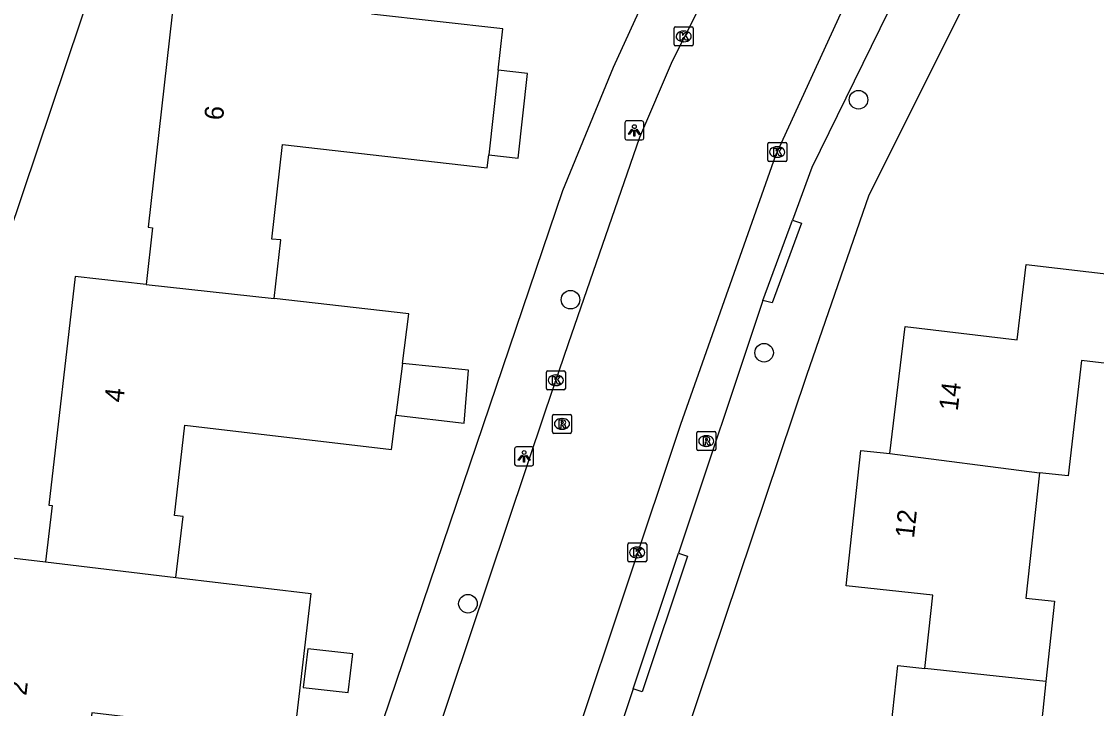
# Model space of a CAD drawing. Extents: x 162398 to 163643, y 386453 to 387397.
# Drawn here: x 162713.1 to 162769.7, y 386684.2 to 386720.4 of the extents above; entities that cross this region are included whole.
import ezdxf

# ---------------------------------------------------------------- set-up
doc = ezdxf.new("R2010")
doc.units = 0
for name, color, linetype in [('IMGEO_Boom', 7, 'Continuous'), ('IMGEO_Kolk', 7, 'Continuous'), ('IMGEO_Lichtpunt', 7, 'Continuous'), ('IMGEO_Pand', 7, 'Continuous'), ('IMGEO_Pand_nummerreeks', 7, 'Continuous'), ('IMGEO_Rijbaan_lokaal_open', 7, 'Continuous'), ('IMGEO_Rioolput', 7, 'Continuous'), ('IMGEO_Voetpad_open', 7, 'Continuous')]:
    doc.layers.add(name, color=color, linetype=linetype)

msp = doc.modelspace()

# ---------------------------------------------------------------- linework, layer by layer
at = {"layer": 'IMGEO_Boom'}
for centre in [(162757.172, 386716.289), (162742.004, 386705.757), (162752.201, 386702.964), (162736.602, 386689.743)]:
    msp.add_circle(centre, 0.489, dxfattribs=at)
at = {"layer": 'IMGEO_Kolk'}
for p, q in [((162747.466, 386719.201), (162747.466, 386720.053)), ((162747.541, 386720.127), (162748.393, 386720.127)), ((162747.954, 386719.907), (162747.979, 386719.907)), ((162748.467, 386720.053), (162748.467, 386719.201)), ((162747.977, 386719.347), (162747.952, 386719.347)), ((162748.393, 386719.127), (162747.541, 386719.127)), ((162752.394, 386713.11), (162752.394, 386713.962)), ((162752.469, 386714.036), (162753.321, 386714.036)), ((162752.882, 386713.816), (162752.907, 386713.816)), ((162753.395, 386713.962), (162753.395, 386713.11)), ((162753.321, 386713.036), (162752.469, 386713.036)), ((162752.905, 386713.256), (162752.88, 386713.256)), ((162740.735, 386701.086), (162740.735, 386701.938)), ((162740.81, 386702.012), (162741.662, 386702.012)), ((162741.223, 386701.792), (162741.248, 386701.792)), ((162741.736, 386701.938), (162741.736, 386701.086)), ((162741.246, 386701.232), (162741.221, 386701.232)), ((162741.662, 386701.012), (162740.81, 386701.012)), ((162745.017, 386692.018), (162745.017, 386692.87)), ((162745.092, 386692.944), (162745.944, 386692.944)), ((162745.505, 386692.724), (162745.53, 386692.724)), ((162746.018, 386692.87), (162746.018, 386692.018)), ((162745.528, 386692.164), (162745.503, 386692.164)), ((162745.944, 386691.944), (162745.092, 386691.944))]:
    msp.add_line(p, q, dxfattribs=at)
for points in [[(162747.466, 386719.201), (162747.466, 386720.053)], [(162747.541, 386720.127), (162748.393, 386720.127)], [(162747.787, 386719.827), (162747.91, 386719.827), (162747.91, 386719.676), (162748.04, 386719.827), (162748.204, 386719.827), (162748.058, 386719.676), (162748.211, 386719.427), (162748.059, 386719.427), (162747.974, 386719.591), (162747.91, 386719.524), (162747.91, 386719.427), (162747.787, 386719.427), (162747.787, 386719.827)], [(162748.467, 386720.053), (162748.467, 386719.201)], [(162748.393, 386719.127), (162747.541, 386719.127)], [(162752.394, 386713.11), (162752.394, 386713.962)], [(162752.469, 386714.036), (162753.321, 386714.036)], [(162752.715, 386713.736), (162752.838, 386713.736), (162752.838, 386713.585), (162752.968, 386713.736), (162753.132, 386713.736), (162752.986, 386713.585), (162753.139, 386713.336), (162752.987, 386713.336), (162752.902, 386713.5), (162752.838, 386713.433), (162752.838, 386713.336), (162752.715, 386713.336), (162752.715, 386713.736)], [(162753.395, 386713.962), (162753.395, 386713.11)], [(162753.321, 386713.036), (162752.469, 386713.036)], [(162740.735, 386701.086), (162740.735, 386701.938)], [(162740.81, 386702.012), (162741.662, 386702.012)], [(162741.056, 386701.712), (162741.179, 386701.712), (162741.179, 386701.561), (162741.309, 386701.712), (162741.473, 386701.712), (162741.327, 386701.561), (162741.48, 386701.312), (162741.328, 386701.312), (162741.243, 386701.476), (162741.179, 386701.409), (162741.179, 386701.312), (162741.056, 386701.312), (162741.056, 386701.712)], [(162741.736, 386701.938), (162741.736, 386701.086)], [(162741.662, 386701.012), (162740.81, 386701.012)], [(162745.017, 386692.018), (162745.017, 386692.87)], [(162745.092, 386692.944), (162745.944, 386692.944)], [(162745.338, 386692.644), (162745.461, 386692.644), (162745.461, 386692.493), (162745.591, 386692.644), (162745.755, 386692.644), (162745.609, 386692.493), (162745.762, 386692.244), (162745.61, 386692.244), (162745.525, 386692.408), (162745.461, 386692.341), (162745.461, 386692.244), (162745.338, 386692.244), (162745.338, 386692.644)], [(162746.018, 386692.87), (162746.018, 386692.018)], [(162745.944, 386691.944), (162745.092, 386691.944)]]:
    msp.add_lwpolyline(points, dxfattribs=at)
for centre, start, end in [((162747.543, 386720.051), 91.552, 178.448), ((162747.543, 386720.051), 91.552, 178.448), ((162748.391, 386720.051), 1.552, 88.448), ((162748.391, 386720.051), 1.552, 88.448), ((162747.543, 386719.203), 181.552, 268.448), ((162747.543, 386719.203), 181.552, 268.448), ((162748.391, 386719.203), 271.552, 358.448), ((162748.391, 386719.203), 271.552, 358.448), ((162752.471, 386713.96), 91.552, 178.448), ((162752.471, 386713.96), 91.552, 178.448), ((162753.319, 386713.96), 1.552, 88.448), ((162753.319, 386713.96), 1.552, 88.448), ((162752.471, 386713.112), 181.552, 268.448), ((162752.471, 386713.112), 181.552, 268.448), ((162753.319, 386713.112), 271.552, 358.448), ((162753.319, 386713.112), 271.552, 358.448), ((162740.812, 386701.936), 91.552, 178.448), ((162740.812, 386701.936), 91.552, 178.448), ((162741.66, 386701.936), 1.552, 88.448), ((162741.66, 386701.936), 1.552, 88.448), ((162740.812, 386701.088), 181.552, 268.448), ((162740.812, 386701.088), 181.552, 268.448), ((162741.66, 386701.088), 271.552, 358.448), ((162741.66, 386701.088), 271.552, 358.448), ((162745.094, 386692.868), 91.552, 178.448), ((162745.094, 386692.868), 91.552, 178.448), ((162745.942, 386692.868), 1.552, 88.448), ((162745.942, 386692.868), 1.552, 88.448), ((162745.094, 386692.02), 181.552, 268.448), ((162745.094, 386692.02), 181.552, 268.448), ((162745.942, 386692.02), 271.552, 358.448), ((162745.942, 386692.02), 271.552, 358.448)]:
    msp.add_arc(centre, 0.0765, start, end, dxfattribs=at)
for centre, major_axis, ratio, start_param, end_param in [((162747.953, 386719.627), (-0.387, 0.002), 0.722429, 4.712389, 7.853982), ((162747.978, 386719.627), (-0.39, 0.002), 0.717154, 1.570796, 4.712389), ((162752.881, 386713.536), (-0.387, 0.002), 0.722429, 4.712389, 7.853982), ((162752.906, 386713.536), (-0.39, 0.002), 0.717154, 1.570796, 4.712389), ((162741.222, 386701.512), (-0.387, 0.002), 0.722429, 4.712389, 7.853982), ((162741.247, 386701.512), (-0.39, 0.002), 0.717154, 1.570796, 4.712389), ((162745.504, 386692.444), (-0.387, 0.002), 0.722429, 4.712389, 7.853982), ((162745.529, 386692.444), (-0.39, 0.002), 0.717154, 1.570796, 4.712389)]:
    msp.add_ellipse(centre, major_axis=major_axis, ratio=ratio, start_param=start_param, end_param=end_param, dxfattribs=at)
at = {"layer": 'IMGEO_Lichtpunt'}
for p, q in [((162744.868, 386715.077), (162744.868, 386714.27)), ((162744.868, 386715.077), (162744.868, 386714.27)), ((162745.77, 386715.172), (162744.962, 386715.172)), ((162745.77, 386715.172), (162744.962, 386715.172)), ((162745.864, 386714.27), (162745.864, 386715.077)), ((162745.864, 386714.27), (162745.864, 386715.077)), ((162744.962, 386714.176), (162745.77, 386714.176)), ((162744.962, 386714.176), (162745.77, 386714.176)), ((162739.062, 386697.909), (162739.062, 386697.102)), ((162739.062, 386697.909), (162739.062, 386697.102)), ((162739.964, 386698.004), (162739.156, 386698.004)), ((162739.964, 386698.004), (162739.156, 386698.004)), ((162740.058, 386697.102), (162740.058, 386697.909)), ((162740.058, 386697.102), (162740.058, 386697.909)), ((162739.156, 386697.008), (162739.964, 386697.008)), ((162739.156, 386697.008), (162739.964, 386697.008))]:
    msp.add_line(p, q, dxfattribs=at)
for points in [[(162745.242, 386714.741), (162745.281, 386714.713), (162745.093, 386714.451), (162745.055, 386714.478), (162745.242, 386714.741)], [(162745.344, 386714.693), (162745.391, 386714.693), (162745.391, 386714.371), (162745.344, 386714.371), (162745.344, 386714.693)], [(162745.454, 386714.713), (162745.492, 386714.74), (162745.679, 386714.478), (162745.64, 386714.45), (162745.454, 386714.713)], [(162739.436, 386697.573), (162739.475, 386697.545), (162739.287, 386697.283), (162739.249, 386697.31), (162739.436, 386697.573)], [(162739.538, 386697.525), (162739.585, 386697.525), (162739.585, 386697.203), (162739.538, 386697.203), (162739.538, 386697.525)], [(162739.648, 386697.545), (162739.686, 386697.572), (162739.873, 386697.31), (162739.834, 386697.282), (162739.648, 386697.545)]]:
    msp.add_lwpolyline(points, dxfattribs=at)
for centre in [(162745.367, 386714.875), (162739.561, 386697.707)]:
    msp.add_circle(centre, 0.0994, dxfattribs=at)
for centre, start, end in [((162744.962, 386715.077), 90, 180), ((162744.962, 386715.077), 90, 180), ((162745.77, 386715.077), 0, 90), ((162745.77, 386715.077), 0, 90), ((162744.962, 386714.27), 180, 270), ((162744.962, 386714.27), 180, 270), ((162745.77, 386714.27), 270, 0), ((162745.77, 386714.27), 270, 360), ((162739.156, 386697.909), 90, 180), ((162739.156, 386697.909), 90, 180), ((162739.964, 386697.909), 0, 90), ((162739.964, 386697.909), 0, 90), ((162739.156, 386697.102), 180, 270), ((162739.156, 386697.102), 180, 270), ((162739.964, 386697.102), 270, 0), ((162739.964, 386697.102), 270, 360)]:
    msp.add_arc(centre, 0.0946, start, end, dxfattribs=at)
at = {"layer": 'IMGEO_Pand'}
for points in [[(162724.697, 386721.66), (162721.171, 386722.057), (162719.763, 386709.572), (162719.989, 386709.546), (162719.653, 386706.562)], [(162738.2, 386717.839), (162738.446, 386720.025), (162731.518, 386720.806)], [(162738.2, 386717.839), (162737.699, 386713.39)], [(162737.699, 386713.39), (162739.247, 386713.216), (162739.748, 386717.665), (162738.2, 386717.839)], [(162726.396, 386705.815), (162726.745, 386708.902), (162726.282, 386708.954), (162726.842, 386713.927), (162737.622, 386712.711), (162737.699, 386713.39)], [(162758.82, 386697.649), (162759.637, 386704.341), (162765.532, 386703.651), (162765.995, 386707.61), (162770.962, 386707.029), (162772.97, 386706.794), (162775.28, 386706.524), (162774.735, 386701.869), (162768.924, 386702.549), (162768.21, 386696.484), (162766.702, 386696.645)], [(162719.653, 386706.562), (162715.909, 386706.984), (162714.527, 386694.94), (162714.704, 386694.919), (162714.356, 386691.953)], [(162719.653, 386706.562), (162726.396, 386705.815)], [(162733.152, 386702.403), (162733.482, 386705.016), (162726.396, 386705.815)], [(162733.152, 386702.403), (162732.808, 386699.677)], [(162732.808, 386699.677), (162736.399, 386699.246), (162736.63, 386702.051), (162733.152, 386702.403)], [(162721.221, 386691.125), (162721.598, 386694.342), (162721.142, 386694.395), (162721.699, 386699.151), (162732.58, 386697.874), (162732.808, 386699.677)], [(162760.672, 386686.327), (162761.087, 386690.195), (162756.529, 386690.684), (162757.294, 386697.812), (162758.82, 386697.649)], [(162758.82, 386697.649), (162766.702, 386696.645)], [(162766.702, 386696.645), (162765.993, 386690.033), (162767.493, 386689.873), (162767.039, 386685.642)], [(162721.221, 386691.125), (162728.337, 386690.29), (162727.451, 386682.742), (162716.795, 386683.992), (162716.238, 386679.246), (162716.64, 386679.199), (162716.14, 386674.932), (162709.333, 386675.731), (162709.678, 386678.67), (162709.318, 386678.712), (162710.919, 386692.356), (162714.356, 386691.953)], [(162714.356, 386691.953), (162721.221, 386691.125)], [(162727.928, 386685.337), (162730.3, 386685.058), (162730.54, 386687.097), (162728.167, 386687.375), (162727.928, 386685.337)], [(162767.039, 386685.642), (162766.876, 386684.117), (162766.343, 386679.145), (162762.799, 386679.525), (162762.236, 386674.275), (162752.728, 386675.295), (162753.556, 386683.015), (162758.807, 386682.452), (162759.239, 386686.481), (162760.672, 386686.327)], [(162767.039, 386685.642), (162760.672, 386686.327)]]:
    msp.add_lwpolyline(points, dxfattribs=at)
at = {"layer": 'IMGEO_Rijbaan_lokaal_open'}
for points in [[(162710.091, 386702.248), (162726.132, 386750), (162726.172, 386750.119), (162726.376, 386750.623), (162726.624, 386751.108), (162726.914, 386751.568), (162727.244, 386752.001), (162727.611, 386752.402), (162728.013, 386752.769), (162728.446, 386753.099), (162728.907, 386753.389), (162729.392, 386753.636), (162729.896, 386753.839), (162730.417, 386753.996), (162730.95, 386754.106), (162731.491, 386754.168), (162732.035, 386754.181), (162732.578, 386754.146), (162758.569, 386751.236), (162760.491, 386750), (162762.044, 386749.001)], [(162730.673, 386670.035), (162730.769, 386670.321), (162740.68, 386699.903), (162741.907, 386703.446), (162745.663, 386714.324), (162747.378, 386718.341), (162751.779, 386727.044), (162755.937, 386733.921), (162764.605, 386747.471)], [(162739.403, 386674.014), (162747.82, 386699.195), (162752.818, 386713.374), (162756.44, 386721.247), (162760.497, 386728.254), (162767.447, 386739.091), (162769.561, 386742.426)]]:
    msp.add_lwpolyline(points, dxfattribs=at)
at = {"layer": 'IMGEO_Rioolput'}
for p, q in [((162741.055, 386698.789), (162741.055, 386699.641)), ((162741.13, 386699.715), (162741.982, 386699.715)), ((162741.543, 386699.495), (162741.568, 386699.495)), ((162742.056, 386699.641), (162742.056, 386698.789)), ((162741.566, 386698.935), (162741.541, 386698.935)), ((162741.982, 386698.715), (162741.13, 386698.715)), ((162748.655, 386697.886), (162748.655, 386698.738)), ((162748.73, 386698.812), (162749.582, 386698.812)), ((162749.143, 386698.592), (162749.168, 386698.592)), ((162749.656, 386698.738), (162749.656, 386697.886)), ((162749.582, 386697.812), (162748.73, 386697.812)), ((162749.166, 386698.032), (162749.141, 386698.032))]:
    msp.add_line(p, q, dxfattribs=at)
for points in [[(162741.055, 386698.789), (162741.055, 386699.641)], [(162741.13, 386699.715), (162741.982, 386699.715)], [(162741.644, 386699.413), (162741.392, 386699.415), (162741.392, 386699.015)], [(162742.056, 386699.641), (162742.056, 386698.789)], [(162741.392, 386699.015), (162741.516, 386699.015), (162741.516, 386699.177), (162741.527, 386699.177)], [(162741.57, 386699.334), (162741.516, 386699.334), (162741.516, 386699.253)], [(162741.516, 386699.253), (162741.568, 386699.253)], [(162741.574, 386699.148), (162741.645, 386699.015), (162741.785, 386699.015), (162741.72, 386699.141)], [(162741.982, 386698.715), (162741.13, 386698.715)], [(162748.655, 386697.886), (162748.655, 386698.738)], [(162748.73, 386698.812), (162749.582, 386698.812)], [(162749.244, 386698.51), (162748.992, 386698.512), (162748.992, 386698.112)], [(162748.992, 386698.112), (162749.116, 386698.112), (162749.116, 386698.274), (162749.127, 386698.274)], [(162749.17, 386698.431), (162749.116, 386698.431), (162749.116, 386698.35)], [(162749.116, 386698.35), (162749.168, 386698.35)], [(162749.656, 386698.738), (162749.656, 386697.886)], [(162749.582, 386697.812), (162748.73, 386697.812)], [(162749.174, 386698.245), (162749.245, 386698.112), (162749.385, 386698.112), (162749.32, 386698.238)]]:
    msp.add_lwpolyline(points, dxfattribs=at)
for centre, radius, start, end in [((162741.132, 386699.639), 0.0765, 91.552, 178.448), ((162741.132, 386699.639), 0.0765, 91.552, 178.448), ((162741.643, 386699.303), 0.109, 350.3612, 89.416), ((162741.98, 386699.639), 0.0765, 1.552, 88.448), ((162741.98, 386699.639), 0.0765, 1.552, 88.448), ((162741.526, 386699.124), 0.0533, 26.0293, 88.6989), ((162741.552, 386699.442), 0.19, 274.7715, 282.9687), ((162741.576, 386699.238), 0.0964, 77.0061, 93.1865), ((162741.59, 386699.295), 0.0378, 276.6634, 79.6772), ((162741.641, 386699.303), 0.112, 277.5842, 350.9817), ((162741.625, 386699.088), 0.108, 29.5134, 73.7905), ((162741.132, 386698.791), 0.0765, 181.552, 268.448), ((162741.132, 386698.791), 0.0765, 181.552, 268.448), ((162741.98, 386698.791), 0.0765, 271.552, 358.448), ((162741.98, 386698.791), 0.0765, 271.552, 358.448), ((162748.732, 386698.736), 0.0765, 91.552, 178.448), ((162748.732, 386698.736), 0.0765, 91.552, 178.448), ((162749.126, 386698.221), 0.0533, 26.0293, 88.6989), ((162749.152, 386698.539), 0.19, 274.7715, 282.9687), ((162749.176, 386698.335), 0.0964, 77.0061, 93.1865), ((162749.19, 386698.392), 0.0378, 276.6634, 79.6772), ((162749.243, 386698.4), 0.109, 350.3612, 89.416), ((162749.241, 386698.4), 0.112, 277.5842, 350.9817), ((162749.225, 386698.185), 0.108, 29.5134, 73.7905), ((162749.58, 386698.736), 0.0765, 1.552, 88.448), ((162749.58, 386698.736), 0.0765, 1.552, 88.448), ((162748.732, 386697.888), 0.0765, 181.552, 268.448), ((162748.732, 386697.888), 0.0765, 181.552, 268.448), ((162749.58, 386697.888), 0.0765, 271.552, 358.448), ((162749.58, 386697.888), 0.0765, 271.552, 358.448)]:
    msp.add_arc(centre, radius, start, end, dxfattribs=at)
for centre, major_axis, ratio, start_param, end_param in [((162741.542, 386699.215), (-0.387, 0.002), 0.722429, 4.712389, 7.853982), ((162741.567, 386699.215), (-0.39, 0.002), 0.717154, 1.570796, 4.712389), ((162749.142, 386698.312), (-0.387, 0.002), 0.722429, 4.712389, 7.853982), ((162749.167, 386698.312), (-0.39, 0.002), 0.717154, 1.570796, 4.712389)]:
    msp.add_ellipse(centre, major_axis=major_axis, ratio=ratio, start_param=start_param, end_param=end_param, dxfattribs=at)
at = {"layer": 'IMGEO_Voetpad_open'}
for points in [[(162762.044, 386749.001), (162752.537, 386734.127), (162746.835, 386723.64), (162744.257, 386717.994), (162741.576, 386711.487), (162727.566, 386670.164)], [(162744.409, 386671.894), (162754.454, 386701.785), (162757.742, 386711.279), (162762.934, 386721.672), (162768.744, 386730.951), (162776.93, 386743.582)], [(162758.738, 386720.921), (162754.722, 386712.724), (162753.698, 386709.944)], [(162753.698, 386709.944), (162754.169, 386709.782), (162752.624, 386705.589), (162752.14, 386705.717)], [(162752.14, 386705.717), (162753.698, 386709.944)], [(162752.14, 386705.717), (162747.69, 386692.411)], [(162747.69, 386692.411), (162748.162, 386692.251), (162745.773, 386685.107), (162745.3, 386685.267)], [(162745.3, 386685.267), (162747.69, 386692.411)], [(162745.3, 386685.267), (162742.231, 386676.09)]]:
    msp.add_lwpolyline(points, dxfattribs=at)

# ---------------------------------------------------------------- texts
at = {"layer": 'IMGEO_Pand_nummerreeks'}
for s, rotation, p in [('6', 83.5659, (162723.695, 386715.174)), ('14', 83.0388, (162762.395, 386699.868)), ('4', 83.457, (162718.445, 386700.315)), ('12', 83.8743, (162760.094, 386693.165)), ('2', 83.3075, (162713.344, 386684.876))]:
    msp.add_text(s, height=1, rotation=rotation, dxfattribs=at).set_placement(p)

doc.saveas('drawing.dxf')
